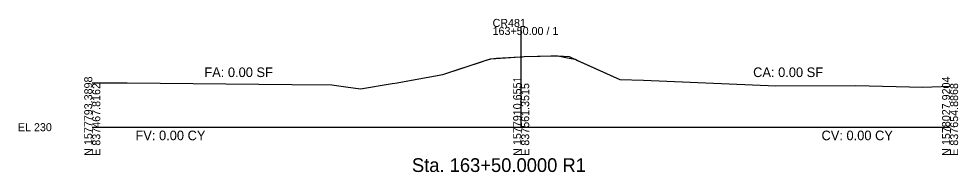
# Model space of a CAD drawing. Extents: x -26 to 303, y -16 to 6048.
# Drawn here: x -25.7 to 302.8, y -15.7 to 37.8 of the extents above; entities that cross this region are included whole.
import ezdxf

# ---------------------------------------------------------------- set-up
doc = ezdxf.new("R2010")
doc.units = 0
for name, color, linetype in [('Draft_XS_Grid', 7, 'Continuous'), ('Draft_XS_Text', 7, 'Continuous'), ('DTM_X_GROUND', 7, 'Continuous'), ('XS_CELL', 7, 'Continuous'), ('XS_SHEET_EW_TX_AREA', 7, 'Continuous'), ('XS_SHEET_EW_TX_VOLUME', 7, 'Continuous')]:
    doc.layers.add(name, color=color, linetype=linetype)

msp = doc.modelspace()

# ---------------------------------------------------------------- linework, layer by layer
at = {"layer": 'DTM_X_GROUND'}
for points in [[(0, 15.54), (12.24, 15.52), (69.78, 14.91), (83.75, 14.77), (88.69, 14.1), (93.79, 13.44), (104.84, 15.23), (106.62, 15.5), (110.31, 16.17), (122.63, 18.35), (137.04, 23.15), (139.39, 23.92), (149.61, 24.57), (150.31, 24.62), (151.04, 24.64), (162.37, 24.96), (162.8, 24.94), (166.77, 24.68), (169.74, 23.33), (184.52, 16.6), (192.76, 16.38), (239.03, 14.47), (267.06, 14.58), (290.51, 13.95), (300, 14.29)], [(0, 15.54), (12.24, 15.52), (69.78, 14.91), (83.75, 14.77), (88.69, 14.1), (93.79, 13.44), (104.84, 15.23), (106.62, 15.5), (110.31, 16.17), (122.63, 18.35), (136.8, 23.07), (137.04, 23.15), (137.46, 23.29), (139.24, 23.87), (139.37, 23.91), (139.39, 23.92), (141.37, 24.05), (149.61, 24.57), (149.9, 24.59), (150, 24.6), (150.31, 24.61), (150.41, 24.61), (151.04, 24.63), (160.39, 24.9), (162.37, 24.96), (162.42, 24.96), (162.8, 24.89), (166.77, 24.14), (168.83, 23.74), (169.09, 23.63), (169.74, 23.33), (171.59, 22.49), (184.52, 16.6), (192.76, 16.38), (239.03, 14.47), (267.06, 14.58), (290.51, 13.95), (300, 14.29)]]:
    msp.add_lwpolyline(points, dxfattribs=at)
at = {"layer": 'XS_CELL'}
for p, q in [((150, 0), (150, 35)), ((0, 0), (150, 0)), ((150, 0), (300, 0))]:
    msp.add_line(p, q, dxfattribs=at)

# ---------------------------------------------------------------- texts
at = {"layer": 'Draft_XS_Grid'}
msp.add_text('-', height=0.0001, dxfattribs=at).set_placement((0, 0))
at = {"layer": 'Draft_XS_Text'}
msp.add_text('Sta. 163+50.0000 R1', height=4.8, dxfattribs=at).set_placement((111.79, -15.65))
at = {"layer": 'XS_CELL'}
for s, p in [('CR481', (140, 35)), ('163+50.00 / 1', (140, 32.2)), ('EL 230', (-26, -1.4))]:
    msp.add_text(s, height=2.8, dxfattribs=at).set_placement(p)
for s, p in [('N 1577793.3898', (0, -10)), ('N 1577910.6551', (150, -10)), ('N 1578027.9204', (300, -10)), ('E 837467.8162', (2.8, -10)), ('E 837561.3515', (152.8, -10)), ('E 837654.8868', (302.8, -10))]:
    msp.add_text(s, height=2.8, rotation=90, dxfattribs=at).set_placement(p)
at = {"layer": 'XS_SHEET_EW_TX_AREA'}
for s, p in [('FA: 0.00 SF', (39.2, 17.5)), ('CA: 0.00 SF', (231.12, 17.5))]:
    msp.add_text(s, height=3.36, dxfattribs=at).set_placement(p)
at = {"layer": 'XS_SHEET_EW_TX_VOLUME'}
for s, p in [('FV: 0.00 CY', (15.11, -4.56)), ('CV: 0.00 CY', (255.03, -4.56))]:
    msp.add_text(s, height=3.36, dxfattribs=at).set_placement(p)

doc.saveas('drawing.dxf')
